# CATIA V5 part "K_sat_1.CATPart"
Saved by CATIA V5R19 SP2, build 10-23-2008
Part number: sat 1
Source: Unknown
Material "Aucun"
Bounding box of the stored display mesh (mm): x -63.515 to 63.515, y -63.573 to 63.573, z -18.921 to 41.193
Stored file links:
  G:\Khaled_CFAO_2011\ST2M\ST2M_GR1\mponsin\Khaled\CAD_ThinkMOTION\K_sat_1.CATPart
  C:\Program Files\Dassault Systemes\B20\win_b64\startup\materials\French\Catalog.CATMaterial
  C:\Users\Socar\Documents\thinkmotion\Final\Diff2.CATProduct
  G:\Khaled_CFAO_2011\ST2M\ST2M_GR1\mponsin\Khaled\CAD_ThinkMOTION\K_mponsin.CATProduct
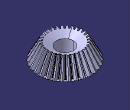
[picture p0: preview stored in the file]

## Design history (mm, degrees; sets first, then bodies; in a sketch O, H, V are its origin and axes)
Parameters
  Z1 = 30 {= External.Zs}
  delta = 26.5651 deg {= atan(External.Zs /External.Zp )}
  a = 20 deg
  m = 4 mm {= External.Module}
  ld = 44.7214 mm {= m *Z1 /(3*2*sin(delta ))}
  dZ = 0 mm
  p = 12.5664 mm {= m * PI}
  rp = 60 mm {= m * Z1 / 2}
  rc = 67.082 mm {= rp / cos( delta )}
  rb = 63.0365 mm {= rc * cos( a )}
  lc = 150 mm {= rc / sin( delta )}
  ha = 4 mm {= m}
  hf = 5 mm {= 1.25 * m}
  rr = 1.4608 mm {= Set2.Offset * 0.7763}
  tc = -0.7576 deg
  ratio = 0.666667 {= 1 - ld / lc / cos( delta )}
External parameters (linked from other documents)
  External.Zp = 60
  External.Zs = 30
  External.Module = 4 mm
Intersect1 "coin de fond": ToIntersect1 Project1, ToIntersect2 Circle4
Point1: type OnCurve, Support Line7, Length 5 {= hf}
Set1 "cones primitifs"
  Line1 "Axe Z": stored without definition
  Point2 "sommet arriere": (0, 0, -30 {= dZ - rp * tan( delta )})
  Point3 "sommet avant": type OnCurve, Support Line1, RefPoint Point2, Length 150 {= lc}
  Line2: type PtPt, FirstPoint Point2, SecondPoint Point3
  Line3: type Angle, RefPoint Point3, Curve Line2, Support zx-plane, Start 0, End 134.1641 {= lc * cos( delta )}, Angle -26.5651 {= -delta}
  Line4: type PtPt, FirstPoint Point2, SecondPoint vertex of Line3, Start 0
  Plane1 "plan_primitif": type OffsetPt, RefPlane xy-plane, RefPoint vertex of Line3
  Intersect2: ToIntersect1 Plane1, ToIntersect2 Line2
  Circle1 "arc primitif": type CtrPt, Start 0, End 30, Center Intersect2, Support Plane1, RefPoint vertex of Line3
  Circle2 "cercle primitif": type CtrRad, Start 0, End 90, Center Intersect2, Support Plane1, Radius 60 {= rp}, FirstDirection (1, 0, 0)
Set2 "profil dent"
  Point4 "point 0": type OnPlane, Support Plane2, RefPoint Point2, H 63.0365, V 0, Direction (1, 0, 0)
  Point5 "point 1": type OnPlane, Support Plane2, RefPoint Point2, H 66.0709, V 0.6451, Direction (1, 0, 0)
  Point6 "point 2": type OnPlane, Support Plane2, RefPoint Point2, H 74.278, V 5.0092, Direction (1, 0, 0)
  Point7 "point 3": type OnPlane, Support Plane2, RefPoint Point2, H 85.116, V 16.077, Direction (1, 0, 0)
  Curve1: Elements (Point4; Point5; Point6; Point7)
  Extrapol1: ToExtrapol Point4, Support Curve1, Length 8 {= 2 * m}
  Plane2: type Normal, Curve Line3, RefPoint Point2
  Symmetry1: Reference vertex of Line3, ToTransfor Point2
  Line5: type PtPt, FirstPoint Point2, SecondPoint Symmetry1
  Point8: type OnCurve, Support Line5, Ratio 0.25
  Line6: type PtPt, FirstPoint Point8, SecondPoint vertex of Line5
  Revol1: Element1 Line6, Line Line1, Angle1 0
  Project1: ToProject Extrapol1, Support Revol1, Direction Line3
  Intersect3: ToIntersect1 Circle1, ToIntersect2 Project1
  Plane3 "plan contact": type 1Line1Pt, RefPoint Intersect3, Line Line1
  Circle3 "cercle primitif": type CtrPt, Start 3 {= 90deg / Z1}, End -3 {= -90deg / Z1}, Center Intersect2, Support Plane1, RefPoint Intersect3
  Plane4 "plan median": type 1Line1Pt, RefPoint vertex of Circle3, Line Line1
  Line7 "droite debut": type PtPt, FirstPoint vertex of Circle3, SecondPoint Point2
  Plane5 "plan_fond": type OffsetPt, RefPlane xy-plane, RefPoint Point1
  Intersect4: ToIntersect1 Plane5, ToIntersect2 Line2
  Circle4 "cercle de fond": type CtrPt, Start 0, End 30, Center Intersect4, Support Plane5, RefPoint Point1
  Point9: type OnCurve, Support Line7, Length -4 {= -ha}
  Plane6 "plan_tete": type OffsetPt, RefPlane xy-plane, RefPoint Point9
  Intersect5: ToIntersect1 Plane6, ToIntersect2 Line2
  Circle5 "cercle de tete": type CtrPt, Start 0, End 30, Center Intersect5, Support Plane6, RefPoint Point9
  Split1 "segment flanc": ToCut Project1, Cutting Plane5
  Split2 "segment fond": ToCut Circle4, Cutting Project1
  Corner1: Element1 Split1, Element2 Split2, Support Revol1, Radius 1.4301 {= Set2.Offset * 0.76}
  Symmetry2: Reference Plane4, ToTransfor Corner1
  Trim1: Element1 Corner1, Element2 Circle5
  Trim2: Element1 Trim1, Element2 Symmetry2
Set3 "surface dent"
  Point10 "fin denture": type OnCurve, Support Line3, Length 44.7214 {= ld}
  Scaling1: Reference Point3, Ratio 0.666667 {= ratio}, ToTransfor Trim2
  Line8: type PtPt, FirstPoint vertex of Scaling1, SecondPoint Point1
  Line9: type PtPt, FirstPoint vertex of Scaling1, SecondPoint vertex of Trim2
  Loft1: Sections (Trim2; Scaling1), Guides (Line8; Line9)
  CircPattern1: of Loft1, instances 30 {= Z1}, angular step 12 {= 360.0*1 deg/CircPattern1.AngularNumber}, axis from Line2
Set4 "flanc dent"
  CircPattern2: of Trim2, instances 30 {= Z1}, angular step 12 {= 360.0*1 deg/CircPattern2.AngularNumber}, axis from Line2
  Join1: Elements (CircPattern2; Trim2)
  Split3: ToCut Revol1, Cutting Join1
  Scaling2: Reference Point3, Ratio 0.666667 {= ratio}, ToTransfor Split3
  Fill1: Boundary edge of Scaling2
  Join2: Elements (Split3; CircPattern1; Scaling2; Fill1; Loft1)
Body1 (main body)
  Sketch1 on zx-plane, origin (0, 0, 0), H (-1, 0, 0), V (0, 0, 1)
    point P1 (-30, -15)
    line L1 (0, 0) -> (0, -18.9213)
    line L2 (0, -18.9213) -> (-30, -18.9213)
    line L3 (-30, -18.9213) -> (-30, -15)
    reference projected point E1 (-30, -15) from Point8
    line L4 (-30, -15) -> (-60, 0)
    point P5 (-60, 0)
    line L5 (0, 0) -> (-60, 0)
    reference projected point E2 (-60, 0) from vertex of Line4
    horizontal: L2 H, L5 H
    vertical: L1 V, L3 V
    coincidence: P1 E1, L1 V, P5 E2
  Shaft1: profile Sketch1, axis Line1, angle 360
  CloseSurface1: CloseElement Join2
  Sketch2 on xy-plane, origin (0, 0, 0), H (1, 0, 0), V (0, 1, 0)
    circle A1 centre (0, 0) radius 20
    radius A1 = 20
  Pocket1: profile Sketch2, direction (0, 0, 1), through (limit type 6), opposite side through (limit type 6)
  Body2
    Sketch3 on zx-plane, origin (0, 0, 0), H (-1, 0, 0), V (0, 0, 1)
      line L1 (0, -30) -> (333.9525, -10)
      point P1 (0, -30)
      point P2 (333.9525, -10)
      line L2 (333.9525, -10) -> (30, -10)
      point P3 (333.9525, -10)
      line L3 (30, -10) -> (30, -20)
      line L4 (30, -20) -> (0, -20)
      point P6 (0, -20)
      line L5 (0, -20) -> (0, -30)
      reference projected point E1 (0, -30) from Point2
      length L3 = 10
      length L4 = 30
      distance L2 H = 10
      length L2 = 303.9525
      coincidence: P1 V, P3 L1, P6 V, P2 P3, P1 E1
      horizontal: L2 H, L4 H
      vertical: L3 V, L5 V
    Shaft2: profile Sketch3, axis Sketch3.L5, angle 360
  Remove1: tool Body2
